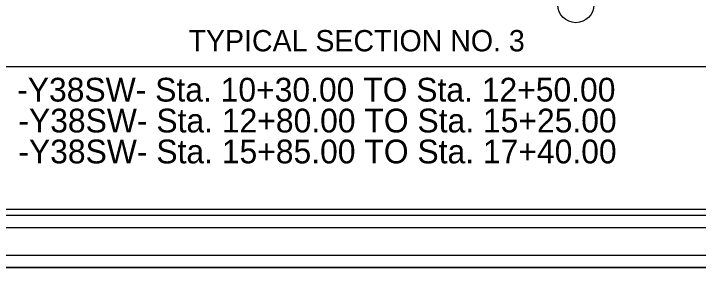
# Model space of a CAD drawing. Extents: x 2294455 to 2294795, y 719276 to 719941.
# Drawn here: x 2294531.2 to 2294590, y 719495.3 to 719517.2 of the extents above; entities that cross this region are included whole.
import ezdxf

# ---------------------------------------------------------------- set-up
doc = ezdxf.new("R2010")
doc.units = 0
for name, color, linetype in [('Default', 7, 'Continuous'), ('Old_Level_1', 7, 'Continuous'), ('Old_Level_11', 7, 'Continuous'), ('Sheet Cutting Line CELL', 7, 'Continuous'), ('Sheet Plot Border Inside CELL', 7, 'Continuous'), ('Sheet Plot Border Outside CELL', 7, 'Continuous'), ('Sheet Typical CELL', 7, 'Continuous'), ('Typical ID Circle CELL', 7, 'Continuous')]:
    doc.layers.add(name, color=color, linetype=linetype)

msp = doc.modelspace()

# ---------------------------------------------------------------- linework, layer by layer
at = {"layer": 'Default'}
msp.add_lwpolyline([(2294454.524, 719715.329), (2294794.524, 719715.329), (2294794.524, 719495.329), (2294454.524, 719495.329)], close=True, dxfattribs=at)
at = {"layer": 'Old_Level_11'}
msp.add_line((2294590.775, 719512.584), (2294528.763, 719512.583), dxfattribs=at)
at = {"layer": 'Sheet Cutting Line CELL'}
msp.add_line((2294791.96, 719496.338), (2294455.16, 719496.338), dxfattribs=at)
at = {"layer": 'Sheet Plot Border Inside CELL'}
msp.add_lwpolyline([(2294790.424, 719710.839), (2294457.124, 719710.839), (2294457.124, 719499.819), (2294790.424, 719499.819)], close=True, dxfattribs=at)
at = {"layer": 'Sheet Plot Border Outside CELL'}
for points in [[(2294793.79, 719718.758), (2294456.99, 719718.758), (2294456.99, 719498.758), (2294793.79, 719498.758)], [(2294794.524, 719715.329), (2294454.524, 719715.329), (2294454.524, 719495.329), (2294794.524, 719495.329)]]:
    msp.add_lwpolyline(points, close=True, dxfattribs=at)
at = {"layer": 'Sheet Typical CELL'}
msp.add_lwpolyline([(2294787.924, 719710.329), (2294487.924, 719710.329), (2294487.924, 719500.329), (2294787.924, 719500.329)], close=True, dxfattribs=at)
at = {"layer": 'Typical ID Circle CELL'}
msp.add_circle((2294579.435, 719517.925), 1.545, dxfattribs=at)

# ---------------------------------------------------------------- texts
at = {"layer": 'Old_Level_1'}
for s, height, rotation, p in [('TYPICAL SECTION NO. 3', 1.83337, 0.00004, (2294546.173, 719513.913)), ('-Y38SW- Sta. 10+30.00 TO Sta. 12+50.00', 2.04545, 360, (2294531.453, 719509.592)), ('-Y38SW- Sta. 12+80.00 TO Sta. 15+25.00', 2.04545, 360, (2294531.555, 719506.935)), ('-Y38SW- Sta. 15+85.00 TO Sta. 17+40.00', 2.04545, 360, (2294531.552, 719504.274))]:
    msp.add_text(s, height=height, rotation=rotation, dxfattribs=at).set_placement(p)

doc.saveas('drawing.dxf')
